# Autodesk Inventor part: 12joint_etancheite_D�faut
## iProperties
Created: 2011-01
Part Number: 12joint_etancheite_D�faut
Document SubType Name: Modeling
Designer: eric
Density: 1 g/cm^3
Mass: 1.00407 g
Surface Area: 53.7215 cm^2
Volume: 1.00407 cm^3
Author: eric
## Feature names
1. Base1
